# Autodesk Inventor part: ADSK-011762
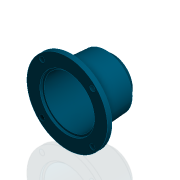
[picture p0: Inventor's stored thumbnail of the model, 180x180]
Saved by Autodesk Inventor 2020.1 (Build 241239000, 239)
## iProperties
Created: 1999-12
Part Number: ADSK-011762
Document SubType Name: Modeling
Designer: tgregory
Material: Aluminum
Density: 2.71 g/cm^3
Appearance: Bearing Blue
Mass: 1157.62 g
Surface Area: 1001.28 cm^2
Volume: 427.165 cm^3
Control State: 0
Checked Out: False
Master: False
Shininess: 25.0
Length Units: 11269
Angle Units: 11279
Time Units: 11290
Mass Units: 11283
Length Display Precision: 3
Angle Display Precision: 2
Compacted: True
Dimensions: 168,3x168,3x95,4 mm
Mass: 1,158 kg
Density: 0.0
Volumn: 0.0
Area: 0.0
PropertySet Name: Model Information
Author: tgregory
Revision Number: -
Title: ADSK-011762
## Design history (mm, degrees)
node "Extrusion1" dims "d1" = 7.9375, "d2" = 0
node "Extrusion2" dims "d4" = 6.5405, "d5" = 65 deg
node "Extrusion3" dims "d6" = 71.4375, "d7" = 4 deg
node "Extrusion4" dims "d9" = 9.525, "d10" = 0
node "Extrusion5" dims "d12" = 4.7625, "d13" = 0
node "Extrusion6" dims "d15" = 71.628, "d16" = -4 deg
node "Extrusion7" dims "d18" = 12.7, "d19" = 0
node "Hole1" dims "d25" = 11, "d26" = 9.525, "d27" = 6.35, "d28" = 60 deg, "d29" = 9.525, "d30" = 118 deg, "d31" = 6
node "Solide1"
node "Corps solides"
node "Corps surfaciques"
sketch "Sketch1"
  geometry: C1 r 7.938 at (-47.625, -52.183) reference; C2 r 41.275 at (-47.625, -52.183)
  constraints: 1 centre point, 1 coincident
  dimensions: "d0" = 82.55 diameter of C2
sketch "Sketch3"
  geometry: C1 r 7.937 at (0, 0) reference; C2 r 41.275 at (0, 0) reference
sketch "Sketch4"
  geometry: C1 r 55.301 at (0, 0) reference
sketch "Sketch5"
  geometry: C1 r 60.297 at (0, 0) reference; C2 r 84.138 at (0, 0)
  constraints: 1 centre point, 1 coincident
  dimensions: "d8" = 168.275 diameter of C2
sketch "Sketch6"
  geometry: C1 r 84.138 at (0, 0) reference; C2 r 57.15 at (0, 0)
  constraints: 1 centre point, 1 coincident
  dimensions: "d11" = 114.3 diameter of C2
sketch "Sketch7"
  geometry: C1 r 57.15 at (0, 0) reference; C2 r 52.784 at (0, 0)
  constraints: 1 centre point, 1 coincident
  dimensions: "d14" = 105.56875 diameter of C2
sketch "Sketch8"
  geometry: C1 r 47.776 at (0, 0) reference; C2 r 7.937 at (0, 0)
  constraints: 1 centre point, 1 coincident
  dimensions: "d17" = 15.87385 diameter of C2
sketch "Sketch9"
  geometry: L1 (0, 0)-(52.759, -52.759); L2 (0, 0)-(78.866, 0); L3 (0, 0)-(52.759, 52.759); L4 (0, 0)-(-52.759, 52.759); L5 (0, 0)-(-52.759, -52.759); L6 (0, 0)-(-79.181, 0); C1 r 84.138 at (0, 0) reference; A1 r 74.612 centre (0, 0) between (52.759, -52.759) and (52.759, 52.759); 4 further points
  constraints: 12 end point, 5 coincident, 4 point on circle, 1 centre point, 1 collinear, 1 horizontal
  dimensions: "d20" = 149.225 diameter of A1; "d21" = 45 deg angle of L1 L2; "d22" = 45 deg angle of L2 L3; "d23" = 45 deg angle of L6 L4 (= d22); "d24" = 45 deg angle of L5 L6 (= d21)
